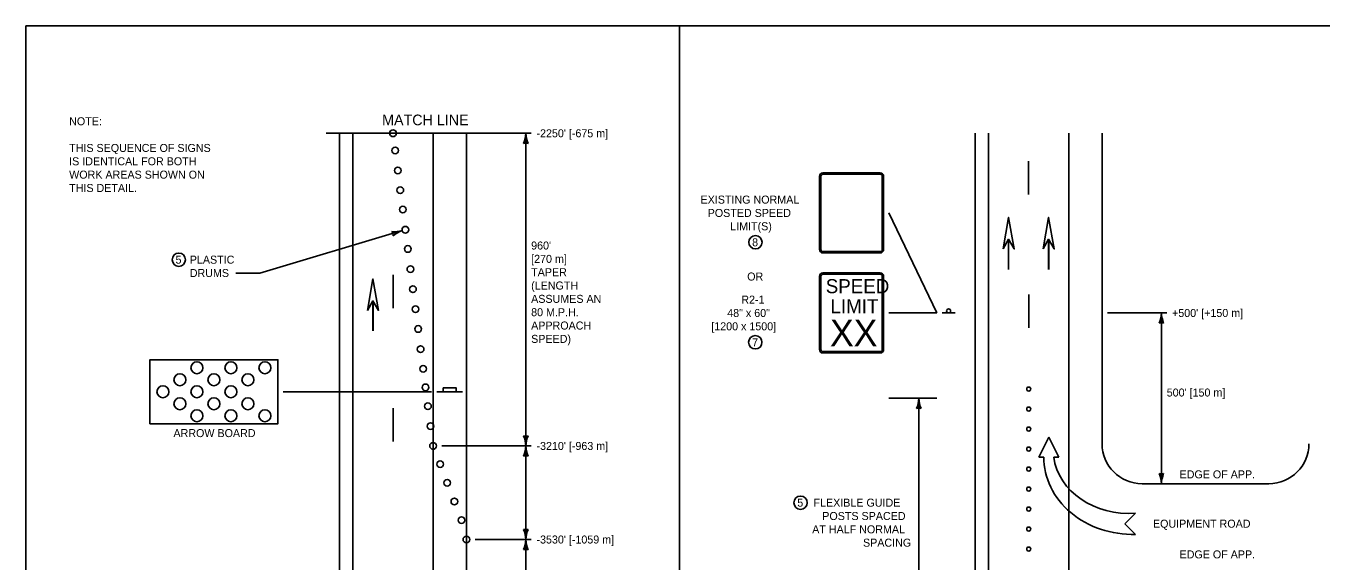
# Model space of a CAD drawing. Extents: x 49991.4 to 50021, y 49987.6 to 50011.4.
# Drawn here: x 49999.38 to 50009.09, y 49994.99 to 49999 of the extents above; entities that cross this region are included whole.
import ezdxf

# ---------------------------------------------------------------- set-up
doc = ezdxf.new("R2010")
doc.units = 0
for name, color, linetype in [('Level 1', 7, 'Continuous'), ('Level 2', 7, 'Continuous'), ('Level 3', 7, 'Continuous'), ('Level 6', 7, 'Continuous')]:
    doc.layers.add(name, color=color, linetype=linetype)

msp = doc.modelspace()

# ---------------------------------------------------------------- linework, layer by layer
at = {"layer": 'Level 1'}
for p, q in [((50001.7353, 49989.3888), (50001.7353, 49998.1941)), ((50001.8353, 49989.3888), (50001.8353, 49998.1941)), ((50002.4353, 49989.3888), (50002.4353, 49998.1941)), ((50002.6853, 49989.3888), (50002.6853, 49998.1941)), ((50006.5002, 49989.2066), (50006.5002, 49998.1941)), ((50006.6002, 49989.2066), (50006.6002, 49998.1941)), ((50007.2002, 49989.2066), (50007.2002, 49998.1941)), ((50007.4502, 49995.8624), (50007.4502, 49998.1941)), ((50006.9, 49997.7359), (50006.9, 49997.9859)), ((50005.3577, 49997.8968), (50005.7877, 49997.8968)), ((50005.3577, 49997.8868), (50005.7877, 49997.8868)), ((50005.3327, 49997.3218), (50005.3327, 49997.8718)), ((50005.3427, 49997.3218), (50005.3427, 49997.8718)), ((50005.8027, 49997.8718), (50005.8027, 49997.3218)), ((50005.8127, 49997.8718), (50005.8127, 49997.3218)), ((50006.7499, 49997.1734), (50006.7499, 49997.3993)), ((50006.7502, 49997.1734), (50006.7502, 49997.3993)), ((50007.0499, 49997.1734), (50007.0499, 49997.3993)), ((50007.0502, 49997.1734), (50007.0502, 49997.3993)), ((50005.7877, 49997.3068), (50005.3577, 49997.3068)), ((50005.7877, 49997.2968), (50005.3577, 49997.2968)), ((50002.1353, 49996.8828), (50002.1353, 49997.1328)), ((50005.3327, 49996.5718), (50005.3327, 49997.1218)), ((50005.3427, 49996.5718), (50005.3427, 49997.1218)), ((50005.3577, 49997.1468), (50005.7877, 49997.1468)), ((50005.3577, 49997.1368), (50005.7877, 49997.1368)), ((50005.8027, 49997.1218), (50005.8027, 49996.5718)), ((50005.8127, 49997.1218), (50005.8127, 49996.5718)), ((50001.9853, 49996.7118), (50001.9853, 49996.9378)), ((50001.9856, 49996.7118), (50001.9856, 49996.9378)), ((50006.9002, 49996.7359), (50006.9002, 49996.9859)), ((50006.2522, 49996.8468), (50006.3482, 49996.8468)), ((50005.7877, 49996.5568), (50005.3577, 49996.5568)), ((50005.7877, 49996.5468), (50005.3577, 49996.5468)), ((50002.6563, 49996.2562), (50002.4643, 49996.2562)), ((50002.1353, 49995.8828), (50002.1353, 49996.1328)), ((50007.0503, 49995.9168), (50006.9753, 49995.7668)), ((50006.9753, 49995.7668), (50007.0503, 49995.9168)), ((50007.1253, 49995.7668), (50007.0503, 49995.9168)), ((50007.0503, 49995.9168), (50007.1253, 49995.7668)), ((50007.0128, 49995.7668), (50006.9753, 49995.7668)), ((50007.0128, 49995.7668), (50006.9753, 49995.7668)), ((50007.1253, 49995.7668), (50007.0878, 49995.7668)), ((50007.1253, 49995.7668), (50007.0878, 49995.7668)), ((50008.7008, 49995.5668), (50007.7502, 49995.5668)), ((50007.702, 49995.3468), (50007.622, 49995.2668)), ((50007.702, 49995.3468), (50007.622, 49995.2668)), ((50007.622, 49995.2668), (50007.702, 49995.1868)), ((50007.622, 49995.2668), (50007.702, 49995.1868))]:
    msp.add_line(p, q, dxfattribs=at)
for points in [[(49999.3835, 49998.9992), (50016.7501, 49998.9992), (50016.7501, 49987.7988), (49999.3835, 49987.7988)], [(50006.7082, 49997.327), (50006.7499, 49997.5635), (50006.7918, 49997.327), (50006.7499, 49997.3992)], [(50007.0082, 49997.327), (50007.0499, 49997.5635), (50007.0918, 49997.327), (50007.0499, 49997.3992)], [(50001.9436, 49996.8654), (50001.9853, 49997.102), (50002.0272, 49996.8654), (50001.9853, 49996.9376)], [(50000.3131, 49996.0162), (50001.2731, 49996.0162), (50001.2731, 49996.4962), (50000.3131, 49996.4962)], [(50000.3131, 49996.0162), (50001.2731, 49996.0162), (50001.2731, 49996.4962), (50000.3131, 49996.4962)], [(50002.5123, 49996.2866), (50002.6083, 49996.2866), (50002.6083, 49996.2562), (50002.5123, 49996.2562)]]:
    msp.add_lwpolyline(points, close=True, dxfattribs=at)
for centre, radius in [((50002.1353, 49998.1941), 0.025), ((50002.1518, 49998.0655), 0.025), ((50002.171, 49997.9151), 0.025), ((50002.1899, 49997.7671), 0.025), ((50002.2085, 49997.6219), 0.025), ((50002.2278, 49997.4712), 0.025), ((50002.247, 49997.3265), 0.025), ((50002.2656, 49997.1759), 0.025), ((50002.2849, 49997.0251), 0.025), ((50002.3042, 49996.8747), 0.025), ((50006.3002, 49996.862), 0.0152), ((50002.3238, 49996.7268), 0.025), ((50002.3424, 49996.5759), 0.025), ((50000.6656, 49996.4362), 0.045), ((50000.6656, 49996.4362), 0.045), ((50000.9206, 49996.4362), 0.045), ((50000.9206, 49996.4362), 0.045), ((50001.1756, 49996.4362), 0.045), ((50001.1756, 49996.4362), 0.045), ((50002.3613, 49996.4283), 0.025), ((50000.5381, 49996.3462), 0.045), ((50000.5381, 49996.3462), 0.045), ((50000.7931, 49996.3462), 0.045), ((50000.7931, 49996.3462), 0.045), ((50001.0481, 49996.3462), 0.045), ((50001.0481, 49996.3462), 0.045), ((50000.4106, 49996.2562), 0.045), ((50000.4106, 49996.2562), 0.045), ((50000.6656, 49996.2562), 0.045), ((50000.6656, 49996.2562), 0.045), ((50000.9206, 49996.2562), 0.045), ((50000.9206, 49996.2562), 0.045), ((50002.3791, 49996.2891), 0.025), ((50006.9002, 49996.2766), 0.015), ((50000.5381, 49996.1662), 0.045), ((50000.5381, 49996.1662), 0.045), ((50000.7931, 49996.1662), 0.045), ((50000.7931, 49996.1662), 0.045), ((50001.0481, 49996.1662), 0.045), ((50001.0481, 49996.1662), 0.045), ((50002.3972, 49996.1474), 0.025), ((50006.9002, 49996.1266), 0.015), ((50000.6656, 49996.0762), 0.045), ((50000.6656, 49996.0762), 0.045), ((50000.9206, 49996.0762), 0.045), ((50000.9206, 49996.0762), 0.045), ((50001.1756, 49996.0762), 0.045), ((50001.1756, 49996.0762), 0.045), ((50002.4163, 49995.9986), 0.025), ((50006.9002, 49995.9766), 0.015), ((50002.4353, 49995.8499), 0.025), ((50006.9002, 49995.8266), 0.015), ((50002.4883, 49995.7135), 0.025), ((50006.9002, 49995.6766), 0.015), ((50002.5415, 49995.5738), 0.025), ((50002.595, 49995.4337), 0.025), ((50006.9002, 49995.5266), 0.015), ((50006.9002, 49995.3766), 0.015), ((50002.6492, 49995.2939), 0.025), ((50002.6853, 49995.1483), 0.025), ((50006.9002, 49995.2266), 0.015), ((50006.9002, 49995.0766), 0.015)]:
    msp.add_circle(centre, radius, dxfattribs=at)
for centre, radius, start, end in [((50005.3577, 49997.8718), 0.025, 90, 180), ((50005.3577, 49997.8718), 0.015, 90, 180), ((50005.7877, 49997.8718), 0.025, 0, 90), ((50005.7877, 49997.8718), 0.015, 0, 90), ((50005.3577, 49997.3218), 0.025, 180, 270), ((50005.3577, 49997.3218), 0.015, 180, 270), ((50005.7877, 49997.3218), 0.025, 270, 0), ((50005.7877, 49997.3218), 0.015, 270, 0), ((50005.3577, 49997.1218), 0.025, 90, 180), ((50005.3577, 49997.1218), 0.015, 90, 180), ((50005.7877, 49997.1218), 0.025, 0, 90), ((50005.7877, 49997.1218), 0.015, 0, 90), ((50005.3577, 49996.5718), 0.025, 180, 270), ((50005.3577, 49996.5718), 0.015, 180, 270), ((50005.7877, 49996.5718), 0.025, 270, 0), ((50005.7877, 49996.5718), 0.015, 270, 0), ((50007.7502, 49995.8668), 0.3, 180, 270), ((50008.7008, 49995.8668), 0.3, 270, 0)]:
    msp.add_arc(centre, radius, start, end, dxfattribs=at)
for centre, major_axis, ratio, start_param, end_param in [((50007.6826, 49995.7669), (-0.6698, 0), 0.866596, 0.000241, 1.599775), ((50007.6826, 49995.7669), (-0.6698, 0), 0.866596, 0.000241, 1.599775), ((50007.6453, 49995.8215), (-0.5612, 0), 0.850316, 0.114953, 1.671938), ((50007.6453, 49995.8215), (-0.5612, 0), 0.850316, 0.114953, 1.671938)]:
    msp.add_ellipse(centre, major_axis=major_axis, ratio=ratio, start_param=start_param, end_param=end_param, dxfattribs=at)
at = {"layer": 'Level 2'}
for centre in [(50004.8523, 49997.3768), (50000.5298, 49997.2464), (50004.851, 49996.6268), (50005.1904, 49995.4245)]:
    msp.add_circle(centre, 0.05, dxfattribs=at)
at = {"layer": 'Level 3'}
for p, q in [((50004.2835, 49998.9992), (50004.2835, 49987.7988)), ((50003.1308, 49989.3603), (50003.1308, 49998.1941)), ((50005.8527, 49997.5968), (50006.2122, 49996.8468)), ((50001.136, 49997.1464), (50002.2039, 49997.464)), ((50001.136, 49997.1464), (50000.956, 49997.1464)), ((50006.2122, 49996.8468), (50005.8527, 49996.8468)), ((50007.895, 49996.8468), (50007.4902, 49996.8468)), ((50007.895, 49995.5668), (50007.895, 49996.8468)), ((50007.895, 49996.8468), (50007.935, 49996.8468)), ((50002.4243, 49996.2562), (50001.3131, 49996.2562)), ((50006.2122, 49996.2068), (50005.8526, 49996.2068)), ((50006.0772, 49996.2068), (50006.0772, 49993.7873)), ((50002.5003, 49995.8498), (50003.1308, 49995.8498)), ((50003.1308, 49995.8498), (50003.1708, 49995.8498)), ((50003.1308, 49995.1483), (50002.7503, 49995.1483)), ((50003.1308, 49995.1483), (50003.1708, 49995.1483))]:
    msp.add_line(p, q, dxfattribs=at)
for centre, radius, start, end in [((50002.9086, 49998.2033), 0.2223, 337.45601, 357.63952), ((50003.3635, 49998.2056), 0.233, 182.82731, 202.07716), ((50003.1308, 49998.0659), 0.0548, 72.13882, 107.86118), ((50002.1447, 49997.6784), 0.2223, 265.23993, 285.42343), ((50002.0818, 49997.4249), 0.0548, 359.92273, 35.64509), ((50002.2859, 49997.246), 0.233, 110.61123, 129.86108), ((50007.6623, 49996.8583), 0.233, 337.92284, 357.17269), ((50008.1171, 49996.856), 0.2223, 182.36048, 202.54399), ((50007.895, 49996.7186), 0.0548, 72.13882, 107.86118), ((50005.8445, 49996.2183), 0.233, 337.92284, 357.17269), ((50006.0772, 49996.0786), 0.0548, 72.13882, 107.86118), ((50006.2993, 49996.216), 0.2223, 182.36048, 202.54399), ((50003.1308, 49995.978), 0.0548, 252.13882, 287.86118), ((50002.8981, 49995.8383), 0.233, 2.82731, 22.07716), ((50002.9086, 49995.859), 0.2223, 337.45601, 357.63952), ((50003.3529, 49995.8406), 0.2223, 157.45601, 177.63952), ((50003.3635, 49995.8613), 0.233, 182.82731, 202.07716), ((50003.1308, 49995.7216), 0.0548, 72.13882, 107.86118), ((50007.6728, 49995.5576), 0.2223, 2.36048, 22.54399), ((50007.895, 49995.695), 0.0548, 252.13882, 287.86118), ((50008.1277, 49995.5553), 0.233, 157.92284, 177.17269), ((50003.1308, 49995.2765), 0.0548, 252.13882, 287.86118), ((50002.8981, 49995.1368), 0.233, 2.82731, 22.07716), ((50003.3529, 49995.1391), 0.2223, 157.45601, 177.63952), ((50002.9086, 49995.1574), 0.2223, 337.45601, 357.63952), ((50003.1308, 49995.02), 0.0548, 72.13882, 107.86118), ((50003.3635, 49995.1597), 0.233, 182.82731, 202.07716)]:
    msp.add_arc(centre, radius, start, end, dxfattribs=at)
at = {"layer": 'Level 6'}
for p, q in [((50001.7353, 49998.1941), (50001.6353, 49998.1941)), ((50001.7353, 49998.1941), (50002.0509, 49998.1941)), ((50001.7353, 49998.1941), (50003.1308, 49998.1941)), ((50002.0538, 49998.1941), (50003.1305, 49998.1941)), ((50003.1308, 49998.1941), (50003.1708, 49998.1941))]:
    msp.add_line(p, q, dxfattribs=at)

# ---------------------------------------------------------------- texts
at = {"layer": 'Level 1'}
for s, height, p in [('SPEED', 0.10512, (50005.3789, 49996.9952)), ('LIMIT', 0.10512, (50005.4143, 49996.8451)), ('XX', 0.19892, (50005.4111, 49996.5978))]:
    msp.add_text(s, height=height, dxfattribs=at).set_placement(p)
at = {"layer": 'Level 2'}
for s, height, p in [('NOTE:', 0.06, (49999.7078, 49998.2541)), ('MATCH LINE', 0.08, (50002.0538, 49998.2541)), ("-2250' [-675 m]", 0.06, (50003.2108, 49998.1641)), ('THIS SEQUENCE OF SIGNS', 0.06, (49999.7078, 49998.0541)), ('IS IDENTICAL FOR BOTH', 0.06, (49999.7078, 49997.9541)), ('WORK AREAS SHOWN ON', 0.06, (49999.7078, 49997.8541)), ('THIS DETAIL.', 0.06, (49999.7078, 49997.7541)), ('EXISTING NORMAL ', 0.06, (50004.4407, 49997.6668)), ('POSTED SPEED ', 0.06, (50004.4941, 49997.5668)), ('LIMIT(S)', 0.06, (50004.6631, 49997.4668)), ('8', 0.06, (50004.8273, 49997.3468)), ("960' ", 0.06, (50003.1708, 49997.3226)), ('5', 0.06, (50000.5049, 49997.2164)), ('PLASTIC', 0.06, (50000.6119, 49997.2164)), ('[270 m]', 0.06, (50003.1708, 49997.2226)), ('DRUMS', 0.06, (50000.6119, 49997.1164)), ('TAPER', 0.06, (50003.1708, 49997.1226)), ('OR', 0.06, (50004.7902, 49997.09)), ('(LENGTH', 0.06, (50003.1708, 49997.0226)), ('ASSUMES AN', 0.06, (50003.1708, 49996.9226)), ('R2-1', 0.06, (50004.7461, 49996.9168)), ('80 M.P.H.', 0.06, (50003.1708, 49996.8226)), ('48" x 60"', 0.06, (50004.6405, 49996.8168)), ("+500' [+150 m]", 0.06, (50007.975, 49996.8168)), ('APPROACH', 0.06, (50003.1708, 49996.7226)), ('[1200 x 1500]', 0.06, (50004.5211, 49996.7168)), ('SPEED)', 0.06, (50003.1708, 49996.6226)), ('7', 0.06, (50004.8272, 49996.5968)), ("500' [150 m]", 0.06, (50007.935, 49996.2204)), ('ARROW BOARD', 0.06, (50000.4896, 49995.9162)), ("-3210' [-963 m] ", 0.06, (50003.2108, 49995.8198)), ('EDGE OF APP.', 0.06, (50008.0313, 49995.6068)), ('5', 0.06, (50005.1655, 49995.3946)), ('FLEXIBLE GUIDE', 0.06, (50005.2873, 49995.3945)), ('POSTS SPACED', 0.06, (50005.3531, 49995.2945)), ('AT HALF NORMAL', 0.06, (50005.2776, 49995.1945)), ('EQUIPMENT ROAD', 0.06, (50007.8319, 49995.2368)), ("-3530' [-1059 m]", 0.06, (50003.2108, 49995.1183)), ('SPACING', 0.06, (50005.6584, 49995.0945)), ('EDGE OF APP.', 0.06, (50008.0313, 49995.0068))]:
    msp.add_text(s, height=height, dxfattribs=at).set_placement(p)

doc.saveas('drawing.dxf')
